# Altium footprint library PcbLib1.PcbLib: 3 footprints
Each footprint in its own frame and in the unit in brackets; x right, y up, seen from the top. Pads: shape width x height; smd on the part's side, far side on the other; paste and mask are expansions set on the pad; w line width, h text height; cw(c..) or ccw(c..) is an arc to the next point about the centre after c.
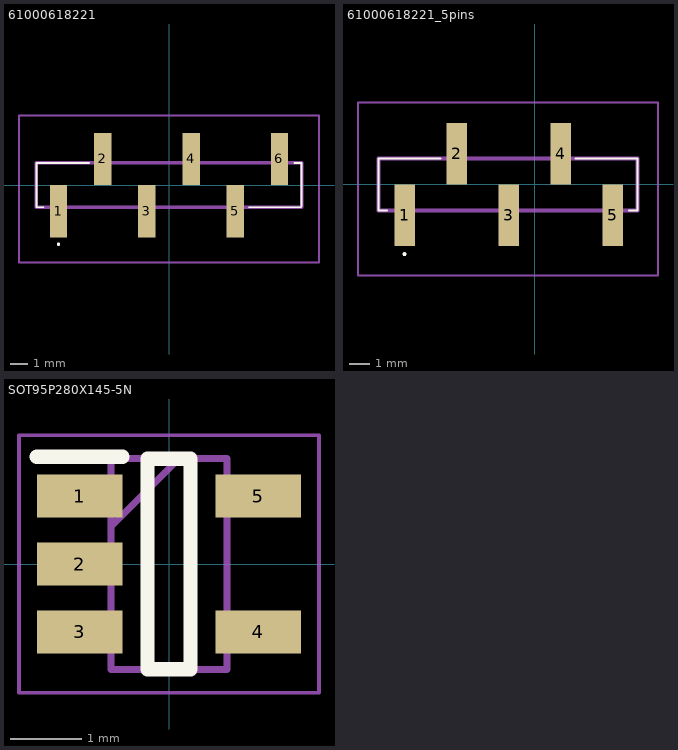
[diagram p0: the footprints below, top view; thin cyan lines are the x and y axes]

## 61000618221 [mm]
pads (6):
  rect 1x3 smd: 1(-6.35,-1.5) 2(-3.81,1.5) 3(-1.27,-1.5) 4(1.27,1.5) 5(3.81,-1.5) 6(6.35,1.5)
Top Overlay:
  lines w0.1: -7.2,-1.27 -7.62,-1.27 -7.62,1.27 -4.6,1.27 ; 4.6,-1.27 7.6,-1.27 7.62,-1.2 7.62,1.27 7.2,1.27 ; -6.4,-3.4 cw(c-6.35,-3.4) -6.3,-3.4 cw(c-6.35,-3.4) -6.4,-3.4
Mechanical 13:
  lines w0.2: -7.62,-1.27 -7.62,1.27 7.62,1.27 7.62,-1.27 -7.62,-1.27
Mechanical 15:
  lines w0.1: -8.62,-4.45 -8.62,4 8.62,4 8.62,-4.45 -8.62,-4.45
3D body "61000618221.stp": height 9.6, standoff 0, extent -7.62,-2.9 7.62,2.9

## 61000618221_5pins [mm]
pads (5):
  rect 1x3 smd: 1(-6.35,-1.5) 2(-3.81,1.5) 3(-1.27,-1.5) 4(1.27,1.5) 5(3.81,-1.5)
Top Overlay:
  lines w0.1: -7.2,-1.27 -7.62,-1.27 -7.62,1.27 -4.6,1.27 ; 2,1.27 5.02,1.27 5.02,-1.27 4.6,-1.27 ; -6.4,-3.4 cw(c-6.35,-3.4) -6.3,-3.4 cw(c-6.35,-3.4) -6.4,-3.4
Mechanical 13:
  lines w0.2: -7.62,-1.27 -7.62,1.27 5.02,1.27 5.02,-1.27 -7.62,-1.27
Mechanical 15:
  lines w0.1: 6,-4.45 -8.62,-4.45 -8.62,4 6.02,4 6.02,-4.45

## SOT95P280X145-5N [mm]
pads (5):
  rect 1.2x0.6 smd: 1(-1.25,0.95) 2(-1.25,0) 3(-1.25,-0.95) 4(1.25,-0.95) 5(1.25,0.95)
Top Overlay:
  lines w0.2: -1.85,1.5 -0.65,1.5 ; -0.3,-1.475 0.3,-1.475 0.3,1.475 -0.3,1.475 -0.3,-1.475
Mechanical 13:
  lines w0.1: -0.812,0.525 0.138,1.475 ; -0.812,-1.475 0.812,-1.475 0.812,1.475 -0.812,1.475 -0.812,-1.475
Mechanical 15:
  lines w0.05: -2.1,-1.8 2.1,-1.8 2.1,1.8 -2.1,1.8 -2.1,-1.8
3D body "TC77-3.3MCTTR.stp": height 1.45, standoff 0, extent -1.4,-1.475 1.4,1.475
